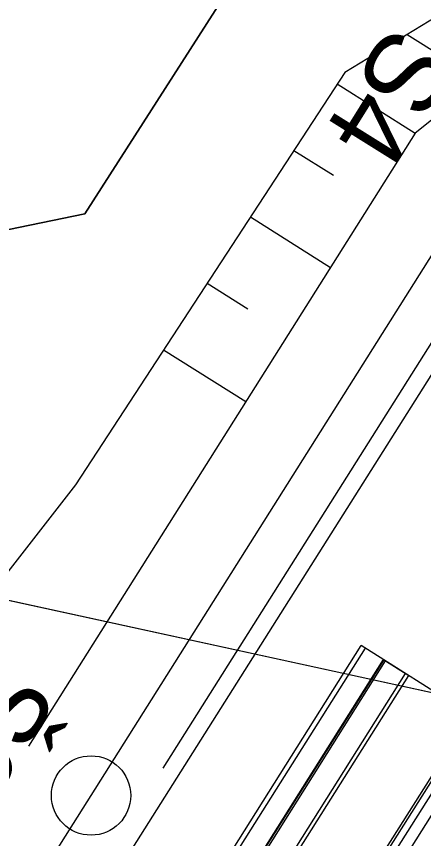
# Model space of a CAD drawing. Extents: x -746176 to -739709, y -1128407 to -1124482.
# Drawn here: x -743175.78 to -743173.21, y -1127095.1 to -1127089.92 of the extents above; entities that cross this region are included whole.
import ezdxf

# ---------------------------------------------------------------- set-up
doc = ezdxf.new("R2010")
doc.units = 0
for name, color, linetype in [('_Zabezpečovací zařízení_trasa', 7, 'Continuous'), ('Hranice parcel', 7, 'Continuous'), ('PREJEZD_KCE', 7, 'Continuous'), ('SVAH', 7, 'Continuous'), ('TRATIVOD', 7, 'Continuous'), ('Vrstva 53', 7, 'Continuous'), ('ZAVER_ZIDKA', 7, 'Continuous')]:
    doc.layers.add(name, color=color, linetype=linetype)

msp = doc.modelspace()

# ---------------------------------------------------------------- linework, layer by layer
at = {"layer": '_Zabezpečovací zařízení_trasa'}
msp.add_lwpolyline([(-743018.819, -1126847.7365), (-743049.2803, -1126895.9513), (-743072.4868, -1126932.7514), (-743098.6471, -1126974.1456), (-743125.9402, -1127017.3839), (-743152.604, -1127059.6082), (-743175.0227, -1127095.1157), (-743199.1633, -1127133.3459), (-743215.971, -1127159.9412), (-743232.818, -1127186.5147), (-743247.4563, -1127209.8113), (-743254.52, -1127221.6389), (-743261.299, -1127233.6914), (-743264.1553, -1127239.1951), (-743264.862, -1127241.1083), (-743267.3367, -1127245.816), (-743268.2889, -1127247.1585), (-743271.7107, -1127253.7504), (-743281.1217, -1127274.1963), (-743291.9232, -1127301.4196), (-743296.7241, -1127315.2221), (-743301.1161, -1127329.1278), (-743306.7868, -1127349.5059)], dxfattribs=at)
at = {"layer": 'Hranice parcel'}
for points in [[(-743080.97, -1126930.41), (-743108.67, -1126985.4), (-743124.8, -1127012.28), (-743175.35, -1127091.16), (-743178.51, -1127091.81)], [(-743159.64, -1127094.74), (-743160.17, -1127095.91), (-743166.78, -1127095.57), (-743176.42, -1127093.47), (-743180.17, -1127093.19), (-743180.08, -1127092.14)]]:
    msp.add_lwpolyline(points, dxfattribs=at)
at = {"layer": 'PREJEZD_KCE'}
for p, q in [((-743173.4637, -1127093.9713), (-743174.4246, -1127095.4934)), ((-743172.8668, -1127094.3482), (-743173.4637, -1127093.9713)), ((-743173.8775, -1127095.8388), (-743172.9166, -1127094.3167)), ((-743173.8636, -1127095.8475), (-743172.9028, -1127094.3255)), ((-743173.8277, -1127095.8702), (-743172.8668, -1127094.3482)), ((-743173.7668, -1127095.9087), (-743172.8059, -1127094.3866))]:
    msp.add_line(p, q, dxfattribs=at)
at = {"layer": 'SVAH'}
for p, q in [((-743173.3157, -1127090.0284), (-743173.0839, -1127090.1747)), ((-743173.7571, -1127090.341), (-743173.2655, -1127090.6514)), ((-743174.0306, -1127090.7597), (-743173.7815, -1127090.9169)), ((-743174.304, -1127091.1783), (-743173.7993, -1127091.497)), ((-743174.5775, -1127091.597), (-743174.3218, -1127091.7584)), ((-743174.8524, -1127092.0178), (-743174.3331, -1127092.3426))]:
    msp.add_line(p, q, dxfattribs=at)
for points in [[(-743171.4836, -1127089.3084), (-743174.8584, -1127094.6542)], [(-743172.839, -1127089.738), (-743173.7096, -1127090.2683), (-743175.408, -1127092.8684), (-743176.5817, -1127094.3736)], [(-743172.238, -1127089.83), (-743173.2655, -1127090.6514), (-743175.7053, -1127094.5163)]]:
    msp.add_lwpolyline(points, dxfattribs=at)
at = {"layer": 'TRATIVOD'}
msp.add_line((-743175.5768, -1127095.2494), (-743175.3099, -1127094.8266), dxfattribs=at)
msp.add_lwpolyline([(-743175.3099, -1127094.8266), (-743172.7963, -1127090.8449)], dxfattribs=at)
msp.add_circle((-743175.3099, -1127094.8266), 0.25, dxfattribs=at)
at = {"layer": 'Vrstva 53'}
msp.add_lwpolyline([(-743032.8, -1126884.17), (-743063.8, -1126932.98), (-743082.27, -1126962.07), (-743093.1, -1126978.92), (-743136.47, -1127047.12), (-743147.78, -1127068.8), (-743159.64, -1127094.74), (-743160.17, -1127095.91), (-743166.78, -1127095.57), (-743176.42, -1127093.47), (-743180.17, -1127093.19), (-743180.08, -1127092.14), (-743178.51, -1127091.81), (-743175.35, -1127091.16), (-743150.075, -1127051.72), (-743124.8, -1127012.28), (-743108.67, -1126985.4), (-743080.97, -1126930.41), (-743079.79, -1126928.05), (-743048.51, -1126865.51), (-743045.12, -1126860.39), (-743029.24, -1126857.99)], dxfattribs=at)
at = {"layer": 'ZAVER_ZIDKA'}
for p, q in [((-743174.567, -1127095.4035), (-743173.6062, -1127093.8814)), ((-743174.5403, -1127095.4203), (-743173.5795, -1127093.8983)), ((-743173.4637, -1127093.9713), (-743173.6062, -1127093.8814)), ((-743174.4274, -1127095.4917), (-743173.4665, -1127093.9696)), ((-743174.4138, -1127095.5002), (-743173.4529, -1127093.9781)), ((-743173.4637, -1127093.9713), (-743173.306, -1127094.0709)), ((-743174.2875, -1127095.5799), (-743173.3266, -1127094.0579)), ((-743174.2668, -1127095.593), (-743173.306, -1127094.0709))]:
    msp.add_line(p, q, dxfattribs=at)

# ---------------------------------------------------------------- texts
at = {"layer": 'TRATIVOD'}
for s, p in [('Š4', (-743173.4167, -1127089.9507)), ('Š2', (-743175.9303, -1127093.9324))]:
    msp.add_text(s, height=0.5, rotation=238, dxfattribs=at).set_placement(p)

doc.saveas('drawing.dxf')
